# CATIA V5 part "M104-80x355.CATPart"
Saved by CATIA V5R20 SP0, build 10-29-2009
Part number: M104-80x355
Source: Unknown
Bounding box of the stored display mesh (mm): x -39.842 to 39.842, y -39.842 to 39.842, z 0 to 355
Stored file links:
  C:\Users\Utente\Desktop\IO LAVORO\3D X SITO CF\X SITO\M104\M104-80x355.CATPart
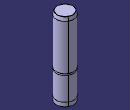
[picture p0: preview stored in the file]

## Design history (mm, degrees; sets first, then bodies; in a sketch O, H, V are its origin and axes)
Body1 (main body)
  Solid1 "PartBody": solid without history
